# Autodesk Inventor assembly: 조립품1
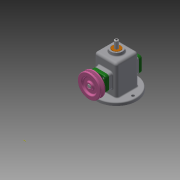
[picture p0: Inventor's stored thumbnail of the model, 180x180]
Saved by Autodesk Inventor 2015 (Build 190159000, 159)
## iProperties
Created: 2021-08
Part Number: 조립품1
Document SubType Name: Assembly
Designer: 10462
Author: 10462
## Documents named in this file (16)
- C:\Users\10462\Desktop\710806V1029\조립품1.iam
- C:\Users\10462\Desktop\710806V1029\V벨트풀리.ipt
- C:\Users\10462\Desktop\710806V1029\고정핀 1.2x8.ipt
- C:\Users\10462\Desktop\710806V1029\뒤커버.ipt
- C:\Users\10462\Desktop\710806V1029\링크.ipt
- C:\Users\10462\Desktop\710806V1029\멈춤나사 M3x8.ipt
- C:\Users\10462\Desktop\710806V1029\베어링 12x32x10.ipt
- C:\Users\10462\Desktop\710806V1029\본체.ipt
- C:\Users\10462\Desktop\710806V1029\볼트 M4.ipt
- C:\Users\10462\Desktop\710806V1029\부시.ipt
- C:\Users\10462\Desktop\710806V1029\슬라이드.ipt
- C:\Users\10462\Desktop\710806V1029\앞커버.ipt
- C:\Users\10462\Desktop\710806V1029\오일 실 12 25 7.ipt
- C:\Users\10462\Desktop\710806V1029\키 4x4x10.ipt
- C:\Users\10462\Desktop\710806V1029\편심축.ipt
- C:\Users\10462\Desktop\710806V1029\핀 5x18.ipt
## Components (3 placed, 3 different names)
1. V벨트풀리:1 — 각도:2
2. 고정핀 1.2x8:1
3. 핀 5x18:1
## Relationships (1: Angle 1)
- 각도:2 [Angle]: V벨트풀리:1
